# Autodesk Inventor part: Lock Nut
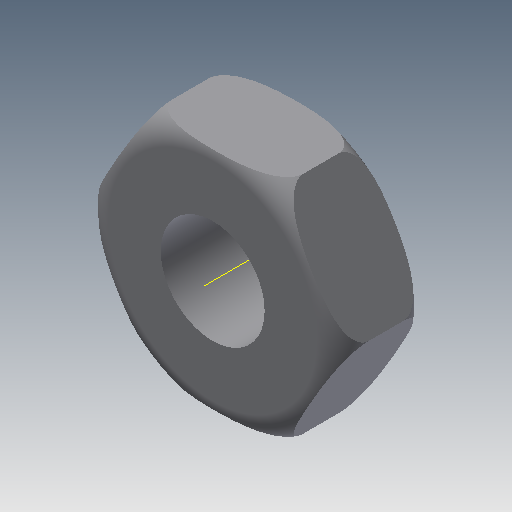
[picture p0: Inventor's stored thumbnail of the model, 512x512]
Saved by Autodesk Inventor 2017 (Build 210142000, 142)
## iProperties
Created: 2009-04
Part Number: Lock Nut
Document SubType Name: Modeling
Designer: Sham
Density: 1 g/cm^3
Material: Generic
Appearance: Default
Mass: 4.65064 g
Surface Area: 21.3319 cm^2
Volume: 4.65064 cm^3
Author: Sham
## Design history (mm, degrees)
sketch "Sketch1"
  geometry: L1 (7.5, 12.99)-(15, 0); L2 (15, 0)-(7.5, -12.99); L3 (7.5, -12.99)-(-7.5, -12.99); L4 (-7.5, -12.99)-(-15, 0); L5 (-15, 0)-(-7.5, 12.99); L6 (-7.5, 12.99)-(7.5, 12.99); C1 r 6 at (0, 0); 1 further point
  constraints: 12 end point, 1 centre point, 1 coincident, 13 other
  dimensions: "d0" = 30 distance of L1.end L4.end; "d1" = 12 diameter of C1
extrude "Extrusion1" new body sketch "Sketch1" distance "d2" = 10; taper "d3" = 0 deg
sketch "Sketch2"
  geometry: L1 (-12, 0)-(-12, -0.022); L2 (-15, 7)-(-15, 3); L3 (0, -2.87)-(0, 12.87) reference; A1 r 3 centre (-12, 7) between (-12, 10) and (-15, 7); A2 r 3 centre (-12, 3) between (-15, 3) and (-12, 0)
  constraints: 4 end point, 4 point on circle, 2 centre point, 1 tangent
revolve "Revolution1" sketch "Sketch2" stored, may be unused: angle "d7" = 90 deg
body "Solid1"
other parameters: "d6" = 90 deg
